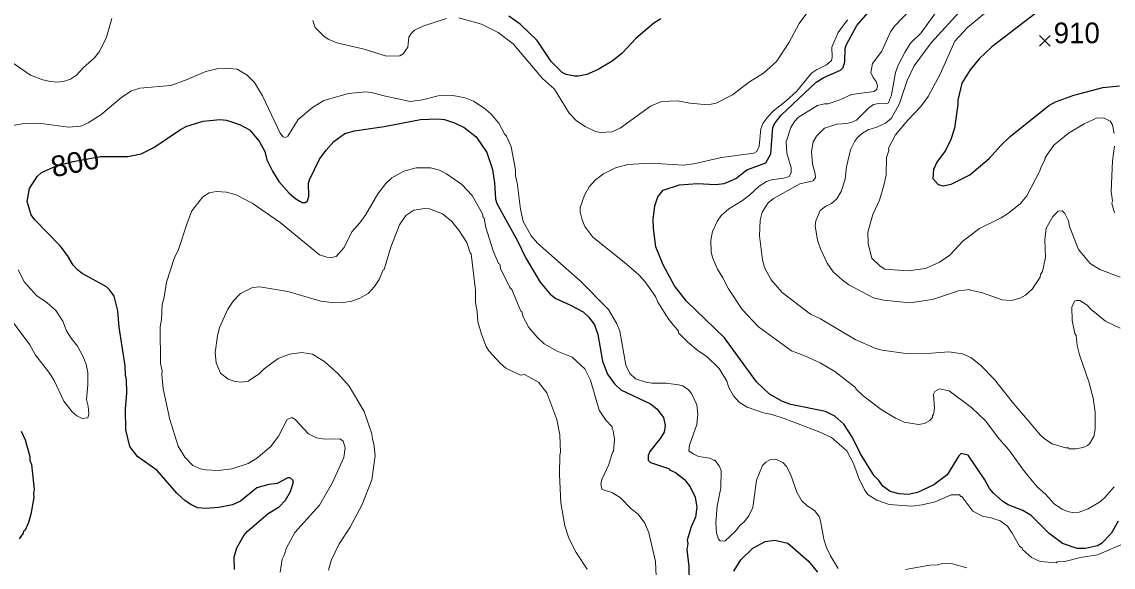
# Model space of a CAD drawing. Extents: x 265.7 to 292.1, y 7676.2 to 7704.2.
# Drawn here: x 273.408 to 277.633, y 7688.129 to 7690.238 of the extents above; entities that cross this region are included whole.
import ezdxf
from ezdxf.enums import TextEntityAlignment as Align

# ---------------------------------------------------------------- set-up
doc = ezdxf.new("R2010")
doc.units = 0
doc.header["$LTSCALE"] = 0.032
for name, color, linetype, lineweight in [('1', 7, 'Continuous', 25), ('2', 7, 'Continuous', 13), ('21', 7, 'Continuous', 25)]:
    doc.layers.add(name, color=color, linetype=linetype, lineweight=lineweight)
doc.layers.add('61', color=7, linetype='Continuous')

msp = doc.modelspace()

# ---------------------------------------------------------------- linework, layer by layer
at = {"layer": '1'}
for points in [[(277.3563, 7690.2882), (277.164, 7690.1414), (277.1146, 7690.0943), (277.0794, 7690.052), (277.0475, 7690.001), (277.0316, 7689.9347), (277.0324, 7689.9188), (277.0196, 7689.8262), (277.0052, 7689.7831), (276.9837, 7689.74), (276.951, 7689.6954), (276.9374, 7689.6666), (276.935, 7689.6323), (276.9558, 7689.6084), (276.9757, 7689.6036), (277.006, 7689.61), (277.0787, 7689.6467), (277.1529, 7689.7089), (277.1967, 7689.7584), (277.2343, 7689.7951), (277.3843, 7689.9148), (277.4098, 7689.9291), (277.4816, 7689.9547), (277.5933, 7689.9834), (277.6572, 7689.9906)], [(275.8825, 7690.2499), (275.8546, 7690.2332), (275.7852, 7690.1733), (275.7309, 7690.1159), (275.6934, 7690.0863), (275.6399, 7690.0536), (275.5952, 7690.0345), (275.5633, 7690.0273), (275.5474, 7690.0273), (275.5154, 7690.0345), (275.5003, 7690.0417), (275.4572, 7690.0848), (275.4037, 7690.1662), (275.3375, 7690.2284), (275.2936, 7690.2603)], [(275.8913, 7689.298), (275.8633, 7689.3682), (275.8538, 7689.4384), (275.8522, 7689.4735), (275.8586, 7689.5262), (275.8705, 7689.5613), (275.8913, 7689.5868), (275.9543, 7689.6076), (276.0245, 7689.6131), (276.0932, 7689.6084), (276.1267, 7689.6124), (276.173, 7689.6323), (276.2145, 7689.665), (276.2887, 7689.6929), (276.3086, 7689.7281), (276.3158, 7689.831), (276.3246, 7689.847), (276.3485, 7689.8773), (276.4834, 7690.0042), (276.5129, 7690.0225), (276.5783, 7690.0512), (276.5879, 7690.0608), (276.5943, 7690.0832), (276.5959, 7690.1358), (276.6023, 7690.1534), (276.6414, 7690.2236), (276.6853, 7690.2739)], [(273.8094, 7688.7394), (273.815, 7688.8032), (273.8142, 7688.8543), (273.8102, 7688.8719), (273.8086, 7688.907), (273.7847, 7689.057), (273.7807, 7689.1208), (273.7663, 7689.1775), (273.7495, 7689.2006), (273.736, 7689.2134), (273.6426, 7689.2644), (273.6251, 7689.2772), (273.6067, 7689.2972), (273.5852, 7689.3347), (273.5572, 7689.3714), (273.4583, 7689.4719), (273.4447, 7689.4911), (273.4296, 7689.5437), (273.4383, 7689.5932), (273.4679, 7689.6403), (273.4846, 7689.6554), (273.5432, 7689.6812), (273.6073, 7689.6982), (273.7128, 7689.7171), (273.819, 7689.7169), (273.8701, 7689.7281), (273.9195, 7689.752), (274.0225, 7689.8222), (274.0472, 7689.835), (274.111, 7689.8533), (274.1749, 7689.8597), (274.2004, 7689.8573), (274.2515, 7689.8406), (274.2898, 7689.8198), (274.3273, 7689.7759), (274.3496, 7689.7368), (274.3568, 7689.7041), (274.3783, 7689.6602), (274.4039, 7689.6203), (274.443, 7689.5757), (274.4693, 7689.5533), (274.494, 7689.5389), (274.5068, 7689.5397), (274.5148, 7689.5453), (274.5196, 7689.5629), (274.5188, 7689.614), (274.522, 7689.6267), (274.5611, 7689.7065), (274.5866, 7689.7416), (274.6169, 7689.7751), (274.6592, 7689.8063), (274.6967, 7689.8158), (274.8116, 7689.8334), (274.9521, 7689.8605), (275.0191, 7689.8629), (275.0447, 7689.8597), (275.083, 7689.8477), (275.1205, 7689.8294), (275.1667, 7689.7927), (275.209, 7689.7329), (275.2306, 7689.6666), (275.2385, 7689.6156), (275.2425, 7689.5517), (275.2473, 7689.535), (275.3271, 7689.3913), (275.3598, 7689.3243), (275.4149, 7689.2309), (275.454, 7689.1847), (275.4763, 7689.1679), (275.5298, 7689.1439), (275.5809, 7689.116), (275.6032, 7689.0953), (275.6256, 7689.0666), (275.6383, 7689.0283), (275.6567, 7688.9261), (275.6758, 7688.875), (275.703, 7688.8383), (275.7277, 7688.8152), (275.8426, 7688.7601), (275.8665, 7688.7418), (275.8921, 7688.7083), (275.8993, 7688.6772), (275.8953, 7688.6516), (275.8801, 7688.6269), (275.8402, 7688.5758), (275.833, 7688.5607), (275.833, 7688.5431), (275.8426, 7688.5335), (275.9152, 7688.5096), (275.916, 7688.5056), (275.9384, 7688.4952), (275.9743, 7688.4681), (275.9958, 7688.4394), (276.015, 7688.3995), (276.0221, 7688.3612)], [(276.3533, 7688.7697), (276.303, 7688.7984), (276.2528, 7688.8463), (276.1291, 7689.0155), (275.9814, 7689.1583), (275.9352, 7689.2166), (275.8913, 7689.298)], [(277.6524, 7688.3069), (277.6252, 7688.259), (277.5885, 7688.2199), (277.5726, 7688.2119), (277.5263, 7688.2016), (277.4944, 7688.2016), (277.4369, 7688.2199), (277.3851, 7688.259), (277.3164, 7688.3292), (277.2837, 7688.3476), (277.2271, 7688.3699), (277.2055, 7688.3835), (277.1696, 7688.4146), (277.1544, 7688.433), (277.1361, 7688.4665), (277.0715, 7688.5622), (277.0451, 7688.5686), (277.0364, 7688.5598), (276.9901, 7688.4864), (276.939, 7688.4473), (276.8752, 7688.4178), (276.8401, 7688.4098), (276.805, 7688.4122), (276.7698, 7688.421), (276.7419, 7688.4417), (276.7259, 7688.4641), (276.7076, 7688.4824), (276.6557, 7688.567), (276.6238, 7688.6309), (276.5911, 7688.6819), (276.5552, 7688.7131), (276.5193, 7688.7314), (276.3852, 7688.7577), (276.3533, 7688.7697)], [(274.0408, 7688.3851), (274.0081, 7688.4154), (273.9323, 7688.5032), (273.8557, 7688.5575), (273.827, 7688.5958), (273.811, 7688.6596), (273.8094, 7688.7394)], [(273.4064, 7688.6548), (273.4216, 7688.6213), (273.4391, 7688.5575), (273.4399, 7688.5415), (273.4463, 7688.5255), (273.4567, 7688.4298), (273.4535, 7688.4138), (273.4551, 7688.3979), (273.4439, 7688.334), (273.4344, 7688.3021), (273.4208, 7688.2726), (273.4144, 7688.267), (273.4136, 7688.2598), (273.3984, 7688.2383)], [(274.2323, 7688.1202), (274.2307, 7688.1681), (274.2403, 7688.2032), (274.2674, 7688.251), (274.2802, 7688.2662), (274.3616, 7688.3364), (274.4047, 7688.3619), (274.4286, 7688.3883), (274.4486, 7688.4218), (274.4589, 7688.4537), (274.4589, 7688.4641), (274.447, 7688.4745), (274.4382, 7688.4745), (274.3967, 7688.4529), (274.3648, 7688.4489), (274.3177, 7688.4354), (274.2555, 7688.3843), (274.2243, 7688.3699), (274.1717, 7688.3596), (274.1206, 7688.3556), (274.0887, 7688.3588), (274.0624, 7688.3707), (274.0408, 7688.3851)], [(276.0221, 7688.3612), (276.0166, 7688.3229), (275.9998, 7688.2846), (275.9846, 7688.2335), (275.9862, 7688.2207), (275.983, 7688.1968), (275.991, 7688.1313)], [(276.1642, 7688.1138), (276.1913, 7688.1569), (276.2384, 7688.2024), (276.2863, 7688.2287), (276.323, 7688.2335), (276.3741, 7688.2215), (276.4522, 7688.1537), (276.4889, 7688.109)], [(275.991, 7688.1313), (275.991, 7688.0803)]]:
    msp.add_lwpolyline(points, dxfattribs=at)
at = {"layer": '2'}
for points in [[(277.737, 7690.8053), (277.6125, 7690.7526), (277.4545, 7690.7112), (277.3651, 7690.672), (277.3316, 7690.6529), (277.271, 7690.6082), (277.2023, 7690.53), (277.1082, 7690.372), (277.0507, 7690.2906), (276.9286, 7690.1574), (276.8624, 7690.0672), (276.8361, 7690.0113), (276.8057, 7689.922), (276.7754, 7689.8653), (276.7523, 7689.8462)], [(277.3164, 7690.5252), (277.2821, 7690.4566), (277.2311, 7690.3704), (277.1648, 7690.2946), (277.0699, 7690.2164), (277.0204, 7690.163), (276.9629, 7690.0353)], [(275.1005, 7690.2531), (275.1883, 7690.2284), (275.2521, 7690.1965), (275.3104, 7690.1526), (275.4245, 7690.0193), (275.4708, 7689.9778), (275.5274, 7689.8853), (275.5553, 7689.8557), (275.5889, 7689.8334), (275.6288, 7689.8142), (275.6495, 7689.8095), (275.6926, 7689.8126), (275.7245, 7689.8262), (275.8426, 7689.9116), (275.8841, 7689.9299), (275.9463, 7689.9323), (275.9942, 7689.9236), (276.0644, 7689.9172), (276.0964, 7689.9228), (276.1594, 7689.9563), (276.2248, 7690.0065), (276.2799, 7690.0401), (276.3294, 7690.084), (276.3772, 7690.1566), (276.4171, 7690.2316), (276.469, 7690.301)], [(276.8528, 7690.289), (276.7866, 7690.2212), (276.7714, 7690.1989), (276.7379, 7690.1247), (276.7012, 7690.0768), (276.6956, 7690.0425), (276.7044, 7690.0225), (276.7164, 7690.0066), (276.7204, 7689.9906), (276.718, 7689.977), (276.7076, 7689.9683), (276.6198, 7689.9571), (276.5751, 7689.9363), (276.5304, 7689.9204), (276.5161, 7689.9212), (276.489, 7689.914), (276.4156, 7689.8693), (276.3996, 7689.8525), (276.3852, 7689.8294), (276.3677, 7689.7736), (276.3693, 7689.7305), (276.3868, 7689.673), (276.3868, 7689.6539), (276.3796, 7689.6403), (276.3581, 7689.6331), (276.3102, 7689.6275), (276.2911, 7689.6211), (276.2623, 7689.602), (276.2272, 7689.5685), (276.1977, 7689.5469), (276.145, 7689.515), (276.1155, 7689.4887), (276.1011, 7689.4687), (276.0828, 7689.4272), (276.0756, 7689.3937), (276.0772, 7689.349), (276.0828, 7689.3267), (276.1019, 7689.282), (276.1227, 7689.2485), (276.1442, 7689.2054), (276.1969, 7689.1256), (276.2607, 7689.0586)], [(273.3753, 7690.0776), (273.4423, 7690.0313), (273.4902, 7690.0137), (273.5189, 7690.0073), (273.5477, 7690.005), (273.5732, 7690.0089), (273.5971, 7690.0169), (273.6195, 7690.0313), (273.6466, 7690.0608), (273.6889, 7690.0975), (273.7097, 7690.1239), (273.7368, 7690.1789), (273.7567, 7690.2507)], [(274.5347, 7690.2428), (274.5435, 7690.2156), (274.577, 7690.1821), (274.5946, 7690.1709), (274.6281, 7690.1574), (274.7334, 7690.1326), (274.8196, 7690.1047), (274.8715, 7690.1063), (274.8851, 7690.1143), (274.9026, 7690.1398), (274.9066, 7690.1789), (274.9154, 7690.1933), (274.9281, 7690.206), (274.9649, 7690.2228), (275.0526, 7690.2515)], [(276.9454, 7690.2723), (276.8895, 7690.1957), (276.8488, 7690.155), (276.8265, 7690.1199), (276.801, 7690.0704), (276.7906, 7690.0417), (276.7754, 7689.9555), (276.7635, 7689.9244), (276.7539, 7689.9204), (276.7252, 7689.922), (276.706, 7689.918), (276.6869, 7689.906), (276.639, 7689.8581), (276.6214, 7689.8494), (276.6023, 7689.8446), (276.564, 7689.8422), (276.5161, 7689.827), (276.4842, 7689.7959), (276.4714, 7689.7743), (276.465, 7689.7368), (276.469, 7689.689), (276.4802, 7689.6507), (276.481, 7689.6355), (276.4714, 7689.6235), (276.4203, 7689.6116), (276.3182, 7689.5549), (276.2982, 7689.5381), (276.2743, 7689.5022), (276.2663, 7689.4703), (276.2639, 7689.4097), (276.2759, 7689.3171), (276.2839, 7689.2884), (276.3094, 7689.2405), (276.3517, 7689.1918), (276.4618, 7689.1072), (276.5001, 7689.0897), (276.6342, 7689.0091), (276.7108, 7688.9764), (276.7395, 7688.9684), (276.8305, 7688.9556), (276.9294, 7688.9564), (276.9965, 7688.962), (277.0499, 7688.954), (277.0826, 7688.9397), (277.1201, 7688.9102), (277.1744, 7688.8543), (277.2422, 7688.7681), (277.3524, 7688.6396), (277.3707, 7688.6229), (277.397, 7688.6061), (277.4481, 7688.5902), (277.4609, 7688.5902), (277.4617, 7688.587), (277.488, 7688.5862), (277.5167, 7688.5918), (277.5335, 7688.5989), (277.5415, 7688.6061), (277.5582, 7688.6341), (277.5638, 7688.6628), (277.563, 7688.7282), (277.5558, 7688.7825), (277.5391, 7688.8463), (277.5024, 7688.9501), (277.4936, 7688.9868), (277.4896, 7689.0251), (277.4848, 7689.033), (277.4744, 7689.0825), (277.4736, 7689.1344), (277.4832, 7689.1575), (277.4904, 7689.1607), (277.5048, 7689.1599), (277.5327, 7689.1416), (277.5486, 7689.1248), (277.6037, 7689.0801), (277.6604, 7689.053)], [(276.6047, 7690.2459), (276.5688, 7690.1965), (276.544, 7690.1406), (276.5448, 7690.1007), (276.5424, 7690.0887), (276.5241, 7690.0712), (276.4842, 7690.0528), (276.465, 7690.0393)], [(274.281, 7690.0313), (274.2419, 7690.0544), (274.1924, 7690.0592), (274.1637, 7690.0568), (274.1206, 7690.0457), (274.0488, 7690.0145), (273.985, 7689.9914), (273.8653, 7689.981), (273.8333, 7689.9714), (273.795, 7689.9467), (273.7144, 7689.8781), (273.6658, 7689.8478), (273.637, 7689.835), (273.5892, 7689.831), (273.4727, 7689.8462), (273.4104, 7689.843), (273.3745, 7689.8374)], [(274.4382, 7689.7959), (274.4294, 7689.7911), (274.4198, 7689.7927), (274.4087, 7689.8071), (274.34, 7689.9523), (274.3089, 7690.0034), (274.281, 7690.0313)], [(276.465, 7690.0393), (276.4076, 7689.9683), (276.3677, 7689.9323), (276.3182, 7689.894), (276.2959, 7689.8709), (276.2775, 7689.8446), (276.2687, 7689.8246)], [(276.9629, 7690.0353), (276.9167, 7689.9491), (276.8887, 7689.91), (276.8377, 7689.8581), (276.7906, 7689.8015), (276.7635, 7689.7488), (276.765, 7689.7408), (276.7555, 7689.7129), (276.7547, 7689.6459), (276.7459, 7689.6044), (276.7283, 7689.5485), (276.7028, 7689.4927), (276.6829, 7689.424), (276.6845, 7689.3794), (276.6996, 7689.3243), (276.7307, 7689.2924), (276.7491, 7689.282), (276.8401, 7689.2756), (276.9071, 7689.2844), (276.9614, 7689.3083), (277.0012, 7689.3355), (277.0523, 7689.3905), (277.1162, 7689.4384), (277.1991, 7689.4799), (277.2247, 7689.4959), (277.2734, 7689.5342), (277.2989, 7689.5653), (277.3492, 7689.6618), (277.3539, 7689.6778), (277.3691, 7689.7049), (277.3699, 7689.7129), (277.4034, 7689.7608), (277.4609, 7689.8079), (277.5207, 7689.843), (277.571, 7689.8669), (277.5981, 7689.8653), (277.6221, 7689.8541), (277.6308, 7689.8398), (277.6372, 7689.8055)], [(276.5688, 7688.1242), (276.5384, 7688.1728), (276.5233, 7688.2048), (276.5137, 7688.2367), (276.5009, 7688.3085), (276.4945, 7688.3245), (276.477, 7688.3476), (276.4491, 7688.3667), (276.4267, 7688.3867), (276.4092, 7688.4186), (276.3836, 7688.4888), (276.3685, 7688.5176), (276.3541, 7688.5343), (276.3278, 7688.5471), (276.3062, 7688.5455), (276.2887, 7688.5351), (276.2759, 7688.5223), (276.2528, 7688.4649), (276.2384, 7688.3596), (276.2224, 7688.3276), (276.2049, 7688.3045), (276.1889, 7688.2917), (276.1698, 7688.267), (276.1299, 7688.2295), (276.1123, 7688.2303), (276.1051, 7688.2367), (276.0972, 7688.2606), (276.0948, 7688.3005), (276.1003, 7688.3644), (276.1139, 7688.4362), (276.1155, 7688.5024), (276.1083, 7688.5208), (276.0916, 7688.5431), (276.086, 7688.5431), (276.0716, 7688.5511), (276.0285, 7688.5575), (276.007, 7688.567), (275.991, 7688.579), (275.9926, 7688.6005), (276.0221, 7688.6803), (276.0253, 7688.7202), (276.0213, 7688.7561), (276.0014, 7688.8), (275.9894, 7688.8152), (275.9671, 7688.8296), (275.9511, 7688.8343), (275.9033, 7688.8399), (275.8474, 7688.8399), (275.8235, 7688.8439), (275.7836, 7688.8575), (275.762, 7688.8774), (275.7461, 7688.9102), (275.7237, 7689.0418), (275.7117, 7689.0698), (275.6798, 7689.1256), (275.5705, 7689.2365), (275.4045, 7689.3825), (275.3798, 7689.4097), (275.3487, 7689.4655), (275.3383, 7689.5134), (275.3263, 7689.6172), (275.3199, 7689.6411), (275.3191, 7689.665), (275.3024, 7689.7544), (275.2848, 7689.7959), (275.2784, 7689.8023), (275.2545, 7689.8462), (275.225, 7689.8813), (275.2018, 7689.902), (275.1564, 7689.9307), (275.1244, 7689.9443), (275.0766, 7689.9531), (275.0207, 7689.9515), (274.9601, 7689.9363), (274.9122, 7689.9299), (274.8164, 7689.9499), (274.7606, 7689.9651), (274.7398, 7689.9667), (274.6728, 7689.9611), (274.577, 7689.9339), (274.534, 7689.9068), (274.4781, 7689.8597), (274.4382, 7689.7959)], [(276.2687, 7689.8246), (276.2631, 7689.7576), (276.2544, 7689.736), (276.2416, 7689.7305), (276.1171, 7689.7137), (276.0102, 7689.6882), (275.9703, 7689.6842), (275.8426, 7689.6914), (275.7548, 7689.6866), (275.707, 7689.673), (275.6607, 7689.6507), (275.6288, 7689.6267), (275.6048, 7689.5996), (275.5865, 7689.5677), (275.5705, 7689.5198), (275.5705, 7689.5038), (275.5777, 7689.4719), (275.5881, 7689.4464), (275.6184, 7689.4049), (275.7405, 7689.3091), (275.7971, 7689.2589), (275.8219, 7689.2325), (275.861, 7689.1759), (275.8705, 7689.1543), (275.9136, 7689.0873), (275.9511, 7689.041), (275.9511, 7689.0354), (275.9862, 7688.9995), (276.0261, 7688.966), (276.0597, 7688.9437), (276.1083, 7688.8974), (276.1371, 7688.8479), (276.1458, 7688.824), (276.1634, 7688.7921), (276.1857, 7688.7673), (276.2161, 7688.7474), (276.2799, 7688.7258), (276.3118, 7688.7194), (276.3597, 7688.7043), (276.4953, 7688.6524), (276.5432, 7688.6301), (276.6023, 7688.579), (276.6286, 7688.5303), (276.6485, 7688.4729), (276.6725, 7688.425), (276.6845, 7688.4082), (276.7188, 7688.3875), (276.7667, 7688.3715), (276.8544, 7688.3643), (276.8943, 7688.3699), (276.9438, 7688.3819), (277.006, 7688.4082), (277.0388, 7688.4082), (277.0435, 7688.4018), (277.0475, 7688.4018), (277.0898, 7688.3452), (277.1305, 7688.3244), (277.1577, 7688.3205), (277.196, 7688.3085), (277.2239, 7688.2869), (277.2422, 7688.2606), (277.2702, 7688.2095), (277.2813, 7688.2024), (277.2821, 7688.1976), (277.3172, 7688.1657), (277.3508, 7688.1513), (277.4122, 7688.1457), (277.417, 7688.1497), (277.4465, 7688.1513), (277.5072, 7688.1657), (277.5726, 7688.1768), (277.6875, 7688.2255)], [(276.7523, 7689.8462), (276.7188, 7689.8302), (276.6853, 7689.8206), (276.6629, 7689.8079), (276.6422, 7689.7895), (276.6326, 7689.7767), (276.6166, 7689.7432)], [(276.6166, 7689.7432), (276.6015, 7689.6778), (276.5959, 7689.6299), (276.5807, 7689.582), (276.5632, 7689.5533), (276.5424, 7689.5358), (276.5209, 7689.5246), (276.4985, 7689.5078), (276.4818, 7689.4687), (276.4802, 7689.4496), (276.4882, 7689.3937), (276.5001, 7689.3602), (276.5265, 7689.3044), (276.5496, 7689.2708), (276.5839, 7689.2397), (276.6103, 7689.2206), (276.706, 7689.1711), (276.7459, 7689.1615), (276.8464, 7689.1511), (276.9342, 7689.1647), (277.0348, 7689.1974), (277.0787, 7689.203), (277.0795, 7689.2006), (277.1241, 7689.1918), (277.2039, 7689.1623), (277.239, 7689.1599), (277.2726, 7689.1687), (277.2933, 7689.1807), (277.3196, 7689.2038), (277.3508, 7689.2501), (277.3523, 7689.2613), (277.3603, 7689.2724), (277.3715, 7689.3283), (277.3691, 7689.3953), (277.3739, 7689.44), (277.3994, 7689.4847), (277.4202, 7689.5054), (277.4361, 7689.507), (277.4465, 7689.4967), (277.4609, 7689.4679), (277.4641, 7689.4464), (277.4992, 7689.357), (277.5447, 7689.3035), (277.5822, 7689.2804), (277.6604, 7689.2509)], [(277.638, 7689.7576), (277.63, 7689.7001), (277.6253, 7689.582), (277.63, 7689.5453), (277.6284, 7689.5358), (277.6388, 7689.4991)], [(275.8354, 7688.2622), (275.8203, 7688.2989), (275.7939, 7688.334), (275.7668, 7688.354), (275.7245, 7688.3979), (275.6926, 7688.4178), (275.6551, 7688.429), (275.6503, 7688.4489), (275.6543, 7688.4681), (275.6806, 7688.5255), (275.695, 7688.5742), (275.699, 7688.5766), (275.7022, 7688.6245), (275.6982, 7688.6564), (275.6934, 7688.6636), (275.6942, 7688.6716), (275.6695, 7688.6971), (275.6439, 7688.7362), (275.6104, 7688.8519), (275.5881, 7688.8958), (275.5386, 7688.9405), (275.4803, 7688.9644), (275.4309, 7688.9931), (275.4037, 7689.0187), (275.3718, 7689.0554), (275.3479, 7689.1001), (275.3447, 7689.1176), (275.3407, 7689.1192), (275.3048, 7689.2022), (275.2976, 7689.211), (275.2609, 7689.2844), (275.2585, 7689.3004), (275.2537, 7689.3028), (275.233, 7689.3522), (275.205, 7689.4432), (275.1979, 7689.4791), (275.1939, 7689.4807), (275.1915, 7689.4951), (275.1524, 7689.5661), (275.1117, 7689.6084), (275.0526, 7689.6499), (275.0255, 7689.6642), (274.9904, 7689.6738), (274.9345, 7689.6738), (274.8867, 7689.6602), (274.8412, 7689.6347), (274.818, 7689.6132), (274.7861, 7689.5725), (274.7398, 7689.4927), (274.7175, 7689.4608), (274.6856, 7689.4256), (274.656, 7689.365), (274.6257, 7689.3307), (274.609, 7689.3267), (274.5898, 7689.3275), (274.5611, 7689.3371), (274.4079, 7689.4615), (274.3002, 7689.5366), (274.2387, 7689.5685), (274.2004, 7689.5796), (274.1621, 7689.582), (274.1334, 7689.5765), (274.1094, 7689.5613), (274.0671, 7689.507), (274.048, 7689.4592), (274.0137, 7689.353), (274.0001, 7689.3267), (273.969, 7689.2309), (273.9594, 7689.1735), (273.9514, 7689.1448), (273.949, 7689.0873), (273.9443, 7689.0586), (273.9459, 7688.9165), (273.9522, 7688.8886), (273.9503, 7688.8744), (273.9554, 7688.8192), (273.981, 7688.6995), (274.0137, 7688.5974), (274.04, 7688.5543), (274.0703, 7688.5215), (274.0999, 7688.5088), (274.119, 7688.5048), (274.1701, 7688.5032), (274.2212, 7688.5096), (274.285, 7688.5303), (274.3169, 7688.5487), (274.372, 7688.5958), (274.4023, 7688.6357), (274.4358, 7688.6995), (274.4542, 7688.7075), (274.4661, 7688.6995), (274.518, 7688.6444), (274.5491, 7688.6293), (274.5818, 7688.6245), (274.6393, 7688.6253)], [(275.5968, 7688.1218), (275.5545, 7688.1856), (275.5258, 7688.2415), (275.5107, 7688.2893), (275.4955, 7688.3771), (275.4899, 7688.4872), (275.4907, 7688.5638), (275.4939, 7688.5718), (275.4907, 7688.6404), (275.4795, 7688.6995), (275.4404, 7688.8032), (275.4085, 7688.8439), (275.3543, 7688.8734), (275.3383, 7688.8718), (275.2824, 7688.8982), (275.2601, 7688.9173), (275.2162, 7688.966), (275.2066, 7688.982), (275.1875, 7689.0299), (275.1739, 7689.0777), (275.1715, 7689.116), (275.1651, 7689.1527), (275.1643, 7689.2006), (275.1484, 7689.3402), (275.1436, 7689.345), (275.1316, 7689.3841), (275.1005, 7689.432), (275.0718, 7689.4671), (275.0367, 7689.4951), (274.9872, 7689.5142), (274.968, 7689.5166), (274.9257, 7689.5102), (274.8954, 7689.4895), (274.8699, 7689.4528), (274.8364, 7689.3666), (274.8108, 7689.2804), (274.8076, 7689.2788), (274.7917, 7689.2421), (274.7733, 7689.215), (274.7486, 7689.187), (274.7175, 7689.1695), (274.6856, 7689.1583), (274.6537, 7689.1527), (274.5986, 7689.1535), (274.5659, 7689.1583), (274.4382, 7689.195), (274.3297, 7689.2134), (274.301, 7689.211), (274.2547, 7689.187), (274.2267, 7689.1583), (274.206, 7689.1272), (274.1733, 7689.0554), (274.1653, 7689.0235), (274.1565, 7688.9596), (274.1613, 7688.9197), (274.1773, 7688.8798), (274.2076, 7688.8559), (274.2339, 7688.8471), (274.2579, 7688.8447), (274.2842, 7688.8487), (274.3281, 7688.8782), (274.3472, 7688.8966), (274.4007, 7688.9357), (274.4446, 7688.9524), (274.4925, 7688.9596), (274.534, 7688.9524), (274.5818, 7688.9229), (274.6313, 7688.8782), (274.676, 7688.8288), (274.7342, 7688.7306), (274.7638, 7688.6452), (274.7654, 7688.6245), (274.7717, 7688.6053), (274.7757, 7688.5591), (274.7638, 7688.4665), (274.7263, 7688.3707), (274.6792, 7688.283), (274.6369, 7688.2191), (274.6066, 7688.1553), (274.5954, 7688.117)], [(273.3945, 7689.2788), (273.4184, 7689.2309), (273.4647, 7689.1791), (273.5054, 7689.1527), (273.5405, 7689.1216), (273.5676, 7689.0809), (273.582, 7689.0426), (273.5995, 7689.0147), (273.6243, 7688.9836), (273.645, 7688.9453), (273.657, 7688.9134), (273.6642, 7688.8814), (273.6642, 7688.8336), (273.6594, 7688.7777), (273.665, 7688.7522), (273.6674, 7688.7202), (273.6642, 7688.7067), (273.6418, 7688.7035), (273.6219, 7688.7147), (273.6035, 7688.7298), (273.5708, 7688.7713), (273.5341, 7688.8511), (273.5134, 7688.883), (273.4615, 7688.9485), (273.4391, 7688.9884), (273.341, 7689.12)], [(276.2607, 7689.0586), (276.3884, 7688.966), (276.4427, 7688.9453), (276.4985, 7688.9189), (276.556, 7688.8854), (276.6358, 7688.824), (276.6374, 7688.8184)], [(276.6374, 7688.8184), (276.6653, 7688.7921), (276.7347, 7688.7386), (276.7906, 7688.7051), (276.8241, 7688.6891), (276.88, 7688.6803), (276.9023, 7688.6843), (276.9231, 7688.6963), (276.9342, 7688.7083), (276.9342, 7688.7147), (276.9382, 7688.7202), (276.9414, 7688.7426), (276.9382, 7688.7984), (276.943, 7688.8088), (276.9614, 7688.8192), (276.9981, 7688.8104), (277.0842, 7688.7466), (277.1393, 7688.6947), (277.1912, 7688.6261), (277.2287, 7688.5822), (277.2901, 7688.4984), (277.3388, 7688.4394), (277.3715, 7688.4106), (277.4066, 7688.3731), (277.4353, 7688.3532), (277.4577, 7688.3436), (277.48, 7688.3388), (277.5016, 7688.342), (277.5359, 7688.354), (277.5838, 7688.3835), (277.6013, 7688.3987), (277.6372, 7688.4394)], [(274.6393, 7688.6253), (274.6521, 7688.6157), (274.6608, 7688.591), (274.6544, 7688.5527), (274.6106, 7688.4569), (274.5611, 7688.3691), (274.4653, 7688.263)], [(274.4653, 7688.263), (274.4326, 7688.2032), (274.4246, 7688.1752), (274.4167, 7688.1601), (274.4087, 7688.109)], [(275.7979, 7687.8034), (275.8195, 7687.8281), (275.8362, 7687.8568), (275.8498, 7687.8952), (275.8673, 7688.0356), (275.861, 7688.1505), (275.8354, 7688.2622)], [(277.0667, 7688.1266), (277.0108, 7688.1417), (276.9709, 7688.1425), (276.955, 7688.1377), (276.9231, 7688.1369), (276.8289, 7688.1202)]]:
    msp.add_lwpolyline(points, dxfattribs=at)
at = {"layer": '21'}
for p, q in [((277.348, 7690.1851), (277.3892, 7690.1439)), ((277.3892, 7690.1851), (277.348, 7690.1439))]:
    msp.add_line(p, q, dxfattribs=at)

# ---------------------------------------------------------------- texts
at = {"layer": '61'}
msp.add_text('910', height=0.08, dxfattribs=at).set_placement((277.4923, 7690.1552), align=Align.CENTER)
at = {"layer": '61', "width": 1.05}
msp.add_text('800', height=0.08, rotation=11.66, dxfattribs=at).set_placement((273.6224, 7689.655), align=Align.CENTER)

doc.saveas('drawing.dxf')
